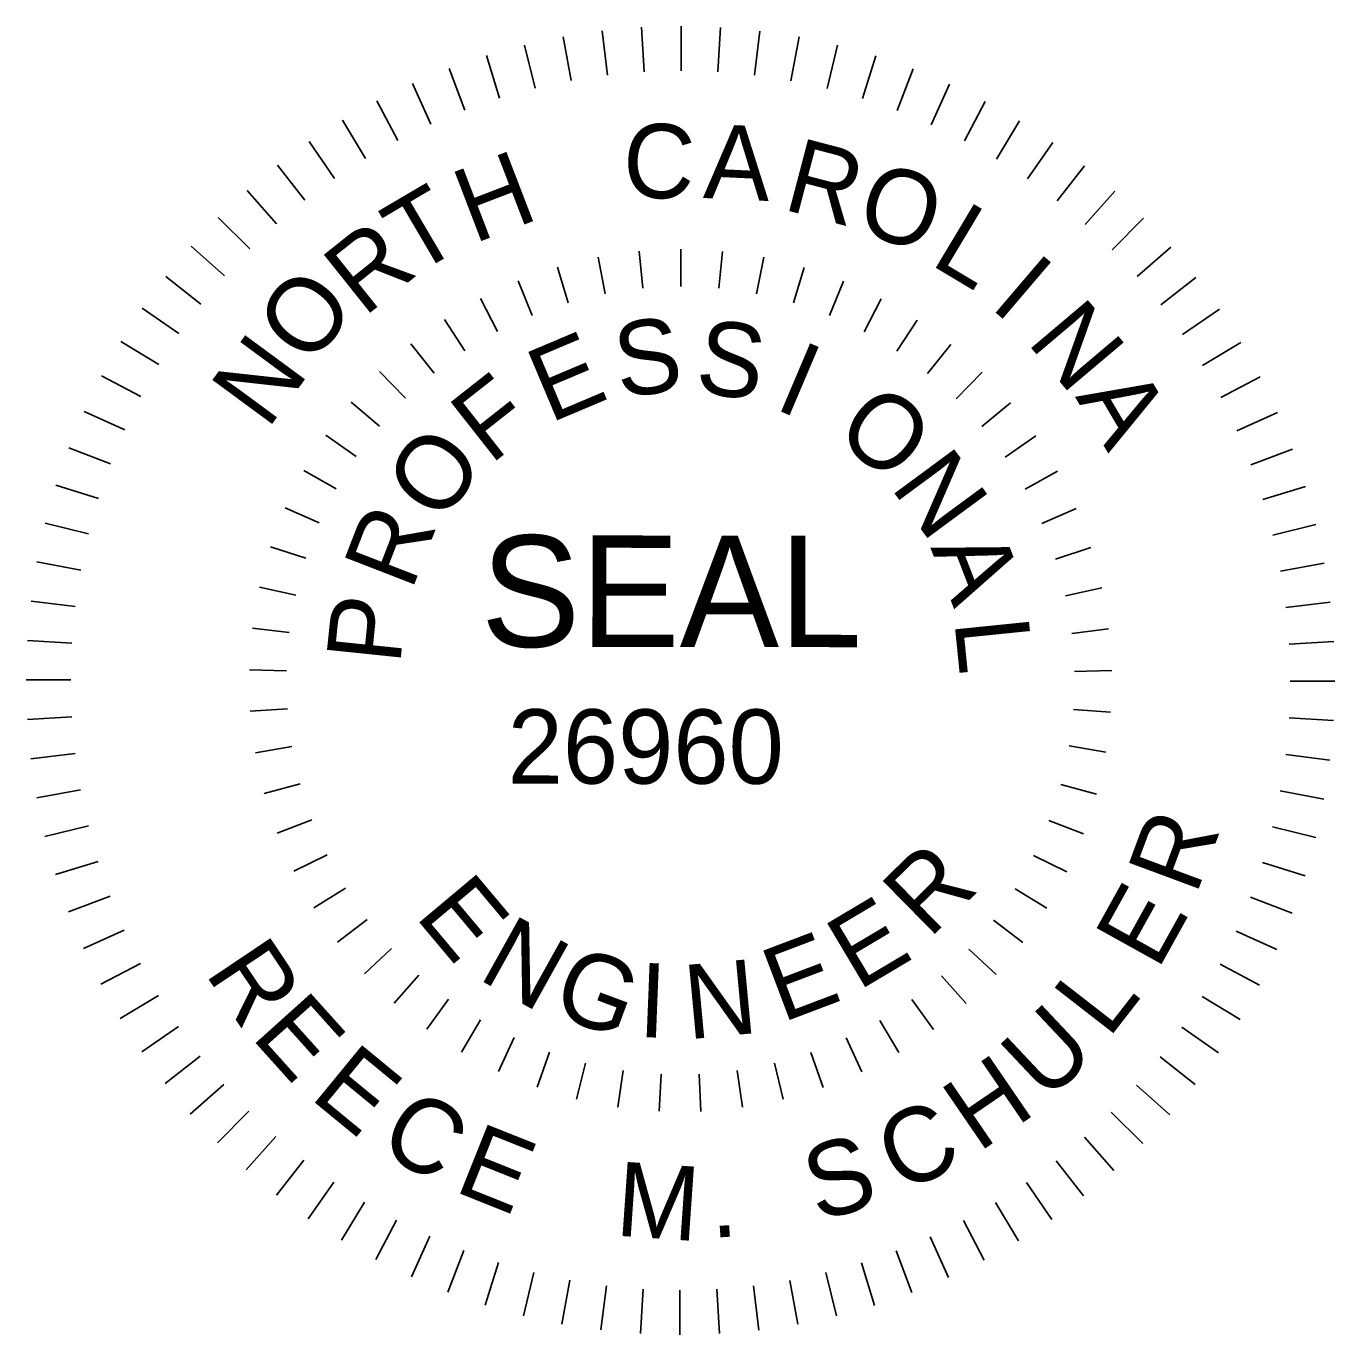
# Model space of a CAD drawing. Extents: x 2294455 to 2294842, y 719496 to 719941.
# Drawn here: x 2294823.72 to 2294839.92, y 719686.18 to 719702.38 of the extents above; entities that cross this region are included whole.
import ezdxf

# ---------------------------------------------------------------- set-up
doc = ezdxf.new("R2010")
doc.units = 0
doc.layers.add('Default', color=7, linetype='Continuous')

msp = doc.modelspace()

# ---------------------------------------------------------------- linework, layer by layer
at = {"layer": 'Default'}
for p, q in [((2294831.824, 719702.382), (2294831.823, 719701.83)), ((2294830.363, 719702.251), (2294830.462, 719701.708)), ((2294830.847, 719702.324), (2294830.913, 719701.776)), ((2294831.334, 719702.368), (2294831.367, 719701.817)), ((2294832.313, 719702.367), (2294832.279, 719701.816)), ((2294832.8, 719702.322), (2294832.733, 719701.775)), ((2294833.284, 719702.249), (2294833.184, 719701.706)), ((2294829.885, 719702.149), (2294830.016, 719701.613)), ((2294833.761, 719702.146), (2294833.63, 719701.61)), ((2294829.413, 719702.018), (2294829.577, 719701.49)), ((2294834.234, 719702.014), (2294834.069, 719701.486)), ((2294828.951, 719701.859), (2294829.147, 719701.342)), ((2294834.695, 719701.854), (2294834.499, 719701.337)), ((2294828.499, 719701.671), (2294828.724, 719701.168)), ((2294835.147, 719701.665), (2294834.921, 719701.162)), ((2294828.059, 719701.458), (2294828.315, 719700.969)), ((2294835.587, 719701.451), (2294835.33, 719700.962)), ((2294827.632, 719701.218), (2294827.917, 719700.746)), ((2294836.013, 719701.21), (2294835.727, 719700.738)), ((2294827.221, 719700.953), (2294827.534, 719700.498)), ((2294836.424, 719700.944), (2294836.11, 719700.491)), ((2294826.827, 719700.663), (2294827.167, 719700.229)), ((2294836.817, 719700.654), (2294836.477, 719700.22)), ((2294826.45, 719700.35), (2294826.816, 719699.937)), ((2294837.193, 719700.34), (2294836.827, 719699.928)), ((2294826.094, 719700.015), (2294826.484, 719699.625)), ((2294837.549, 719700.004), (2294837.158, 719699.615)), ((2294825.758, 719699.659), (2294826.171, 719699.293)), ((2294837.884, 719699.648), (2294837.471, 719699.282)), ((2294830.795, 719699.522), (2294830.883, 719699.071)), ((2294831.305, 719699.596), (2294831.35, 719699.139)), ((2294831.821, 719699.621), (2294831.821, 719699.161)), ((2294831.821, 719699.161), (2294831.821, 719699.621)), ((2294832.337, 719699.595), (2294832.292, 719699.138)), ((2294832.846, 719699.521), (2294832.758, 719699.069)), ((2294830.295, 719699.4), (2294830.425, 719698.958)), ((2294833.347, 719699.397), (2294833.216, 719698.956)), ((2294825.444, 719699.283), (2294825.879, 719698.943)), ((2294829.807, 719699.229), (2294829.98, 719698.802)), ((2294833.834, 719699.225), (2294833.66, 719698.799)), ((2294838.197, 719699.272), (2294837.762, 719698.932)), ((2294829.34, 719699.012), (2294829.552, 719698.604)), ((2294834.301, 719699.007), (2294834.088, 719698.6)), ((2294825.154, 719698.89), (2294825.608, 719698.576)), ((2294838.487, 719698.878), (2294838.032, 719698.564)), ((2294828.894, 719698.751), (2294829.146, 719698.365)), ((2294834.746, 719698.745), (2294834.494, 719698.36)), ((2294824.888, 719698.48), (2294825.36, 719698.193)), ((2294828.477, 719698.448), (2294828.765, 719698.088)), ((2294835.163, 719698.442), (2294834.874, 719698.083)), ((2294838.752, 719698.467), (2294838.279, 719698.181)), ((2294824.647, 719698.053), (2294825.136, 719697.796)), ((2294828.091, 719698.106), (2294828.412, 719697.776)), ((2294835.549, 719698.099), (2294835.227, 719697.77)), ((2294838.992, 719698.04), (2294838.503, 719697.784)), ((2294827.739, 719697.729), (2294828.09, 719697.432)), ((2294835.9, 719697.721), (2294835.548, 719697.425)), ((2294824.433, 719697.613), (2294824.936, 719697.387)), ((2294839.205, 719697.6), (2294838.702, 719697.374)), ((2294827.425, 719697.319), (2294827.803, 719697.057)), ((2294836.213, 719697.311), (2294835.834, 719697.049)), ((2294824.245, 719697.162), (2294824.761, 719696.965)), ((2294839.393, 719697.148), (2294838.876, 719696.952)), ((2294827.153, 719696.882), (2294827.554, 719696.657)), ((2294836.484, 719696.873), (2294836.082, 719696.649)), ((2294824.085, 719696.7), (2294824.613, 719696.535)), ((2294839.552, 719696.685), (2294839.024, 719696.522)), ((2294826.923, 719696.419), (2294827.345, 719696.235)), ((2294836.713, 719696.41), (2294836.291, 719696.227)), ((2294823.953, 719696.228), (2294824.489, 719696.096)), ((2294839.683, 719696.213), (2294839.147, 719696.082)), ((2294826.741, 719695.936), (2294827.178, 719695.795)), ((2294836.895, 719695.927), (2294836.457, 719695.786)), ((2294823.85, 719695.75), (2294824.393, 719695.65)), ((2294839.785, 719695.735), (2294839.242, 719695.636)), ((2294826.604, 719695.439), (2294827.054, 719695.34)), ((2294837.03, 719695.43), (2294836.581, 719695.331)), ((2294823.776, 719695.266), (2294824.324, 719695.2)), ((2294839.858, 719695.251), (2294839.31, 719695.186)), ((2294826.517, 719694.931), (2294826.973, 719694.875)), ((2294823.731, 719694.779), (2294824.282, 719694.746)), ((2294837.116, 719694.921), (2294836.66, 719694.866)), ((2294839.902, 719694.764), (2294839.351, 719694.732)), ((2294823.716, 719694.29), (2294824.268, 719694.289)), ((2294826.479, 719694.416), (2294826.939, 719694.404)), ((2294837.154, 719694.406), (2294836.694, 719694.395)), ((2294839.916, 719694.275), (2294839.364, 719694.275)), ((2294823.731, 719693.8), (2294824.281, 719693.833)), ((2294826.491, 719693.901), (2294826.95, 719693.933)), ((2294837.14, 719693.891), (2294836.682, 719693.924)), ((2294839.901, 719693.786), (2294839.35, 719693.819)), ((2294836.627, 719693.473), (2294837.081, 719693.396)), ((2294823.775, 719693.313), (2294824.322, 719693.379)), ((2294826.553, 719693.388), (2294827.006, 719693.465)), ((2294839.856, 719693.298), (2294839.308, 719693.365)), ((2294826.663, 719692.884), (2294827.107, 719693.005)), ((2294836.966, 719692.875), (2294836.523, 719692.996)), ((2294823.847, 719692.83), (2294824.39, 719692.928)), ((2294839.782, 719692.815), (2294839.24, 719692.915)), ((2294826.823, 719692.393), (2294827.253, 719692.556)), ((2294836.806, 719692.384), (2294836.376, 719692.548)), ((2294823.949, 719692.352), (2294824.486, 719692.482)), ((2294839.679, 719692.337), (2294839.143, 719692.469)), ((2294824.08, 719691.879), (2294824.608, 719692.043)), ((2294827.029, 719691.921), (2294827.441, 719692.125)), ((2294836.599, 719691.912), (2294836.188, 719692.117)), ((2294839.548, 719691.865), (2294839.02, 719692.03)), ((2294827.278, 719691.47), (2294827.67, 719691.712)), ((2294836.349, 719691.462), (2294835.958, 719691.704)), ((2294824.239, 719691.417), (2294824.756, 719691.613)), ((2294839.388, 719691.403), (2294838.871, 719691.6)), ((2294827.571, 719691.044), (2294827.937, 719691.324)), ((2294836.055, 719691.037), (2294835.689, 719691.316)), ((2294824.427, 719690.965), (2294824.93, 719691.191)), ((2294839.199, 719690.952), (2294838.696, 719691.178)), ((2294827.904, 719690.651), (2294828.24, 719690.963)), ((2294835.722, 719690.643), (2294835.386, 719690.956)), ((2294824.64, 719690.525), (2294825.13, 719690.781)), ((2294838.985, 719690.511), (2294838.496, 719690.769)), ((2294828.272, 719690.29), (2294828.578, 719690.634)), ((2294835.353, 719690.283), (2294835.048, 719690.628)), ((2294824.88, 719690.098), (2294825.353, 719690.384)), ((2294828.674, 719689.967), (2294828.945, 719690.338)), ((2294834.95, 719689.961), (2294834.68, 719690.333)), ((2294838.744, 719690.085), (2294838.272, 719690.372)), ((2294829.105, 719689.683), (2294829.339, 719690.08)), ((2294834.519, 719689.678), (2294834.285, 719690.075)), ((2294825.146, 719689.687), (2294825.6, 719690)), ((2294838.478, 719689.675), (2294838.024, 719689.989)), ((2294829.562, 719689.443), (2294829.757, 719689.861)), ((2294834.061, 719689.439), (2294833.868, 719689.857)), ((2294825.435, 719689.293), (2294825.87, 719689.633)), ((2294830.04, 719689.248), (2294830.193, 719689.682)), ((2294833.583, 719689.245), (2294833.43, 719689.679)), ((2294838.188, 719689.281), (2294837.754, 719689.622)), ((2294830.641, 719689.547), (2294830.53, 719689.1)), ((2294831.04, 719689.001), (2294831.107, 719689.456)), ((2294832.582, 719688.999), (2294832.517, 719689.454)), ((2294833.089, 719689.098), (2294832.979, 719689.545)), ((2294825.748, 719688.916), (2294826.162, 719689.282)), ((2294831.553, 719688.95), (2294831.575, 719689.41)), ((2294832.069, 719688.949), (2294832.048, 719689.409)), ((2294837.874, 719688.905), (2294837.461, 719689.272)), ((2294826.083, 719688.56), (2294826.474, 719688.95)), ((2294837.538, 719688.55), (2294837.148, 719688.94)), ((2294826.439, 719688.225), (2294826.806, 719688.637)), ((2294837.182, 719688.215), (2294836.816, 719688.628)), ((2294826.815, 719687.911), (2294827.155, 719688.345)), ((2294836.805, 719687.901), (2294836.466, 719688.336)), ((2294827.208, 719687.62), (2294827.523, 719688.074)), ((2294836.411, 719687.612), (2294836.098, 719688.066)), ((2294827.619, 719687.354), (2294827.906, 719687.826)), ((2294836.001, 719687.347), (2294835.715, 719687.819)), ((2294828.045, 719687.113), (2294828.302, 719687.602)), ((2294835.574, 719687.106), (2294835.318, 719687.596)), ((2294828.485, 719686.899), (2294828.712, 719687.402)), ((2294835.133, 719686.893), (2294834.908, 719687.397)), ((2294828.937, 719686.711), (2294829.134, 719687.227)), ((2294834.681, 719686.706), (2294834.486, 719687.222)), ((2294829.399, 719686.551), (2294829.563, 719687.079)), ((2294834.219, 719686.546), (2294834.055, 719687.075)), ((2294829.871, 719686.419), (2294830.002, 719686.955)), ((2294830.349, 719686.316), (2294830.448, 719686.859)), ((2294833.269, 719686.313), (2294833.17, 719686.856)), ((2294833.747, 719686.416), (2294833.616, 719686.952)), ((2294830.832, 719686.243), (2294830.899, 719686.79)), ((2294831.319, 719686.198), (2294831.353, 719686.749)), ((2294831.809, 719686.182), (2294831.809, 719686.734)), ((2294832.298, 719686.197), (2294832.265, 719686.748)), ((2294832.785, 719686.241), (2294832.719, 719686.788))]:
    msp.add_line(p, q, dxfattribs=at)

# ---------------------------------------------------------------- texts
for s, height, rotation, p in [('C', 0.919, 357.3039, (2294831.086, 719700.275)), ('A', 0.919, 357.3039, (2294832.091, 719700.256)), ('R', 0.919, 345.2946, (2294833.065, 719700.119)), ('H', 0.919, 21.0146, (2294829.256, 719699.686)), ('O', 0.919, 342.2378, (2294833.955, 719699.854)), ('T', 0.919, 30.4466, (2294828.515, 719699.286)), ('L', 0.919, 329.1015, (2294834.89, 719699.443)), ('R', 0.919, 38.6075, (2294827.896, 719698.772)), ('I', 0.919, 319.5261, (2294835.631, 719698.909)), ('O', 0.919, 51.6643, (2294827.23, 719698.154)), ('N', 0.919, 310.2316, (2294836.092, 719698.475)), ('S', 0.919, 7.5951, (2294831.061, 719697.779)), ('S', 0.919, 352.2989, (2294831.979, 719697.855)), ('N', 0.919, 53.6237, (2294826.701, 719697.377)), ('E', 0.919, 22.8914, (2294830.197, 719697.464)), ('I', 0.919, 337.0026, (2294832.957, 719697.655)), ('F', 0.919, 38.1876, (2294829.461, 719696.945)), ('O', 0.919, 321.7064, (2294833.698, 719697.297)), ('A', 0.919, 300.4641, (2294836.698, 719697.796)), ('O', 0.919, 53.4838, (2294828.849, 719696.204)), ('N', 0.919, 306.4101, (2294834.405, 719696.68)), ('R', 0.919, 68.7801, (2294828.484, 719695.378)), ('SEAL', 1.3802, 359.947, (2294829.344, 719694.699)), ('A', 0.919, 291.1139, (2294834.909, 719695.927)), ('P', 0.919, 84.0763, (2294828.344, 719694.467)), ('L', 0.919, 275.8176, (2294835.206, 719695.016)), ('26960', 0.9194, 359.947, (2294829.676, 719693.007)), ('R', 0.919, 69.6194, (2294838.196, 719691.611)), ('R', 0.919, 44.5119, (2294834.893, 719691.075)), ('E', 0.919, 310.0171, (2294828.518, 719691.365)), ('E', 0.919, 60.9466, (2294837.722, 719690.683)), ('E', 0.919, 30.7408, (2294834.016, 719690.435)), ('N', 0.919, 330.8721, (2294829.29, 719690.598)), ('R', 0.919, 303.882, (2294825.92, 719690.664)), ('E', 0.919, 20.7549, (2294833.073, 719690.044)), ('G', 0.919, 339.6384, (2294830.189, 719690.166)), ('I', 0.919, 357.7332, (2294831.284, 719689.871)), ('N', 0.919, 5.3628, (2294831.908, 719689.839)), ('L', 0.919, 52.154, (2294837.113, 719689.837)), ('E', 0.919, 311.9538, (2294826.489, 719689.87)), ('U', 0.919, 43.2714, (2294836.342, 719689.052)), ('E', 0.919, 320.5966, (2294827.213, 719689.12)), ('H', 0.919, 34.3888, (2294835.504, 719688.432)), ('C', 0.919, 329.2691, (2294828.041, 719688.486)), ('C', 0.919, 25.5662, (2294834.544, 719687.926)), ('E', 0.919, 338.2416, (2294828.995, 719687.967)), ('S', 0.919, 16.5636, (2294833.515, 719687.578)), ('M', 0.919, 356.0369, (2294830.998, 719687.412)), ('.', 0.919, 3.7793, (2294832.199, 719687.382))]:
    msp.add_text(s, height=height, rotation=rotation, dxfattribs=at).set_placement(p)

doc.saveas('drawing.dxf')
